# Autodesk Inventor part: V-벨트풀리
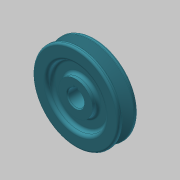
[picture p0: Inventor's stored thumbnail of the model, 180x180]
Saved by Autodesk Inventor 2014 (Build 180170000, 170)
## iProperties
Created: 2019-01
Part Number: V-벨트풀리
Material: 알루미늄 6061
Document SubType Name: Modeling
Designer: mduedu
Density: 1 g/cm^3
Appearance: 커뎃 파란색
Author: mduedu
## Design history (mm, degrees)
sketch "스케치1"
  geometry: L1 (-10, 0)-(10, 0); L2 (10, 0)-(10, 44.5); L3 (10, 44.5)-(-10, 44.5); L4 (-10, 44.5)-(-10, 0); L5 (0, 0)-(0, 44.5); L6 (-5.976, 44.5)-(-2.154, 32); L7 (-2.154, 32)-(2.154, 32); L8 (2.154, 32)-(5.976, 44.5); L9 (-10, 40)-(10, 40); 3 further points
  constraints: 18 end point, 8 point on line, 3 perpendicular, 2 midpoint, 2 parallel, 1 coincident, 1 horizontal, 1 other
  dimensions: "d0" = 89 diameter of L3 L1; "d2" = 20 distance of L2.end L3.end; "d3" = 34 deg angle of L8 L6; "d4" = 9.2 distance of point (4.6, 40) point (-4.6, 40); "d5" = 80 diameter of L9 L1; "d6" = 8 distance between parallel lines of L7 L9; "d7" = 4.5 distance between parallel lines of L3 L9 (derived)
revolve "회전1" sketch "스케치1" stored, may be unused: angle "d8" = 90 deg
fillet "모깎기1" dims "d9" = 0.5, "d10" = 1, "d11" = 2
sketch "스케치2"
  geometry: C1 r 17.5 at (0, 0); 1 further point
  constraints: 1 centre point, 1 coincident
  dimensions: "d12" = 35 diameter of C1
extrude "돌출1" join sketch "스케치2" distance "d13" = 10; taper "d14" = 0 deg
sketch "스케치3"
  geometry: L1 (-2.5, 8.124)-(2.5, 8.124); L2 (2.5, 8.124)-(2.5, 10.8); L3 (2.5, 10.8)-(-2.5, 10.8); L4 (-2.5, 10.8)-(-2.5, 8.124); A1 r 8.5 centre (0, 0) between (-2.5, 8.124) and (2.5, 8.124); 1 further point
  constraints: 8 end point, 2 parallel, 2 point on circle, 1 centre point, 1 coincident, 1 horizontal, 1 perpendicular
  dimensions: "d15" = 17 diameter of A1; "d16" = 5 distance of L2.end L3.end; "d17" = 19.3 dimension on A1 L3
extrude "돌출2" cut sketch "스케치3" stored distance "d18" = 10; taper "d19" = 0 deg
node "작업 평면1"
sketch "스케치4"
  geometry: L1 (-10, 17.5)-(-10, -17.5) reference; 2 further points
  constraints: 1 horizontal alignment
  dimensions: "d21" = 8 distance from line of point (-2, 0) L1
hole "구멍1" sketch "스케치4" at (-2, 0) diameter "d22" = 2.459; stored, may be unused: countersink angle "d26" = 90 deg, drill point angle "d28" = 118 deg; dims "d23" = 6, "d24" = 4, "d25" = 2, "d27" = 8
chamfer "모따기1" distance "d29" = 1; stored, may be unused: second distance "d30" = 2, angle "d31" = 45 deg
sketch "스케치5"
  geometry: C1 r 17.5 at (0, 0) reference; C2 r 30 at (0, 0); 1 further point
  constraints: 1 centre point, 1 coincident
  dimensions: "d37" = 60 diameter of C2
extrude "돌출3" cut sketch "스케치5" distance "d34" = 6; taper "d35" = 0 deg
fillet "모깎기4" dims "d38" = 3
node "솔리드1"
mirror "대칭1"
